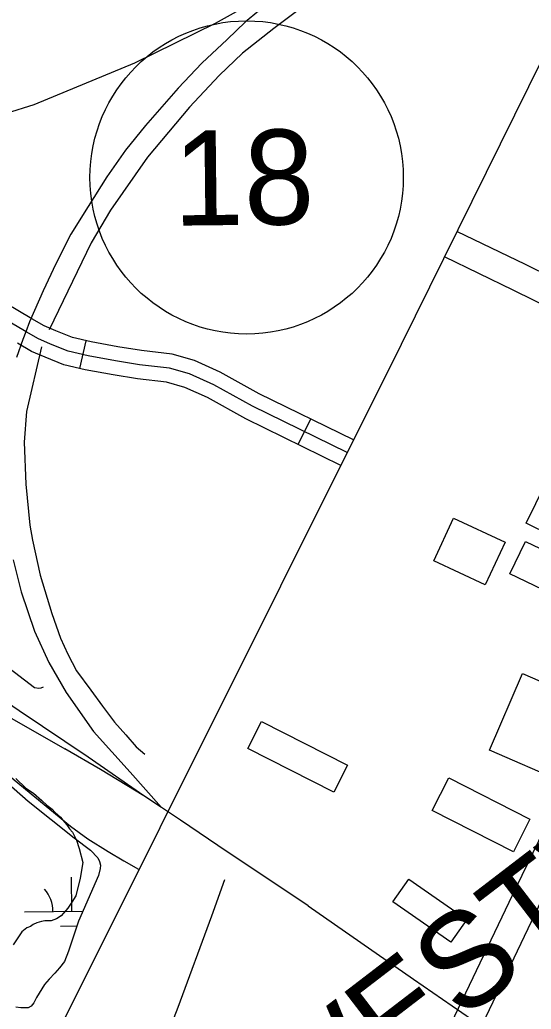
# Model space of a CAD drawing. Extents: x 3651524 to 3689615, y 505651 to 531377.
# Drawn here: x 3656690 to 3657229, y 514939 to 515981 of the extents above; entities that cross this region are included whole.
import ezdxf

# ---------------------------------------------------------------- set-up
doc = ezdxf.new("R2010")
doc.units = 0
for name, color, linetype in [('V-BLDG-OTLN', 7, 'Continuous'), ('V-CHAN-NAID', 7, 'Continuous'), ('V-RAIL-TRAK', 7, 'Continuous'), ('V-ROAD-CNTR', 7, 'Continuous'), ('V-ROAD-IDEN', 7, 'Continuous'), ('V-SITE-VEGE', 7, 'Continuous'), ('V-TOPO-SHOR', 7, 'Continuous'), ('V-WETL-SWMP', 7, 'Continuous')]:
    doc.layers.add(name, color=color, linetype=linetype)

msp = doc.modelspace()

# ---------------------------------------------------------------- linework, layer by layer
at = {"layer": 'V-BLDG-OTLN'}
for points in [[(3657357.467, 515385.145), (3657223.63, 515451.061), (3657254.288, 515513.313), (3657292.12, 515494.681), (3657274.796, 515459.504), (3657301.996, 515446.108), (3657309.987, 515462.334), (3657378.793, 515428.448)], [(3657201.339, 515431.182), (3657180.482, 515386.202), (3657126.287, 515411.332), (3657147.144, 515456.312)], [(3657335.971, 515335.602), (3657206.418, 515397.568), (3657222.827, 515431.874), (3657352.38, 515369.907)], [(3657219.76, 515292.521), (3657297.426, 515258.969), (3657262.587, 515178.324), (3657184.921, 515211.876)], [(3657021.078, 515167.723), (3656930.539, 515213.539), (3656944.981, 515242.077), (3657035.52, 515196.262)], [(3657210.063, 515104.874), (3657124.565, 515148.419), (3657142.036, 515182.722), (3657227.534, 515139.176)], [(3657099.87, 515076.061), (3657160.99, 515033.587), (3657144.295, 515009.562), (3657083.174, 515052.035)]]:
    msp.add_lwpolyline(points, close=True, dxfattribs=at)
at = {"layer": 'V-RAIL-TRAK'}
for points in [[(3657027.03, 516055.879), (3656964.812, 516016.027), (3656895.915, 515977.383), (3656811.245, 515935.815), (3656705.116, 515891.768), (3656588.044, 515855.281)], [(3656968.943, 516013.28), (3656927.987, 515979.378), (3656908.535, 515960.776), (3656882.145, 515935.698), (3656857.161, 515909.473), (3656822.648, 515870.01), (3656801.605, 515843.88), (3656781.987, 515815.814), (3656762.244, 515784.791), (3656744.036, 515755.576), (3656728.242, 515724.252), (3656714.936, 515695.947), (3656700.555, 515663.277), (3656696.596, 515652.758), (3656693.52, 515644.583), (3656686.884, 515625.7)], [(3656820.952, 515163.739), (3656762.412, 515204.408), (3656689.573, 515253.538), (3656620.506, 515300.41), (3656553.242, 515345.759), (3656473.403, 515400.984), (3656409.302, 515444.843), (3656315.785, 515507.174), (3656233.592, 515562.538), (3656163.614, 515606.648), (3656109.569, 515639.594), (3656060.358, 515666.98), (3655990.169, 515703.645), (3655925.596, 515734.771), (3655821.772, 515778.057), (3655754.041, 515802.254)], [(3656683.188, 515412.579), (3656691.695, 515378.693), (3656705.9, 515337.457), (3656720.701, 515304.117), (3656739.004, 515272.635), (3656767.983, 515231.561), (3656806.373, 515188.737), (3656839.343, 515151.588)], [(3656593.037, 515303.071), (3656633.64, 515275.476), (3656681.752, 515245.127), (3656737.529, 515213.397)], [(3656839.343, 515151.588), (3656820.952, 515163.739), (3656775.257, 515191.408), (3656737.529, 515213.397)], [(3656994.076, 515047.747), (3656898.764, 515111.405), (3656859.357, 515138.11), (3656839.343, 515151.588)], [(3656994.076, 515047.747), (3657105.069, 514970.799), (3657166.102, 514928.428), (3657251.364, 514871.481), (3657382.891, 514781.73), (3657445.666, 514738.898), (3657502.343, 514700.625), (3657624.534, 514620.046), (3657696.96, 514574.038), (3657732.292, 514553.056), (3657795.889, 514518.578), (3657843.355, 514494.899), (3657922.647, 514459.028), (3658024.488, 514414.992), (3658106.425, 514381.161), (3658188.117, 514347.101), (3658276.069, 514310.043), (3658352.66, 514278.241), (3658430.613, 514244.758), (3658553.331, 514191.666), (3658647.596, 514153.723), (3658745.038, 514111.927), (3658817.017, 514083.077)]]:
    msp.add_lwpolyline(points, dxfattribs=at)
at = {"layer": 'V-ROAD-CNTR'}
for p, q in [((3656753.363, 515614.091), (3656760.122, 515643.32)), ((3656983.59, 515533.901), (3656996.764, 515560.854))]:
    msp.add_line(p, q, dxfattribs=at)
for points in [[(3657821.364, 517115.979), (3657494.654, 516454.852), (3657091.838, 515639.148), (3656710.83, 514875.472), (3656430.01, 514305.598), (3656056.096, 513550.048), (3655742.777, 512921.615)], [(3655716.186, 515785.202), (3655800.868, 515755.908), (3655912.687, 515711.634), (3656007.159, 515667.133), (3656037.175, 515651.483), (3656067.596, 515635.258), (3656114.681, 515607.156), (3656202.069, 515549.224), (3656316.766, 515474.798), (3656450.209, 515383.084), (3656482.187, 515358.901), (3656506.308, 515337.065), (3656541.46, 515302.628), (3656616.681, 515239.917), (3656684.412, 515180.535), (3656743.501, 515131.86), (3656761.956, 515118.659), (3656783.335, 515105.334), (3656799.958, 515095.211), (3656815.427, 515086.576)], [(3657035.098, 515525.421), (3656935.269, 515574.216), (3656894.752, 515596.905), (3656869.132, 515608.237), (3656847.847, 515614.384), (3656816.351, 515618.054), (3656791.032, 515621.974), (3656762.352, 515627.408), (3656741.117, 515632.319), (3656722.665, 515639.819), (3656709.237, 515645.46), (3656695.297, 515653.555), (3656653.889, 515677.857), (3656523.525, 515769.898)], [(3657471.799, 515600.837), (3657222.975, 515723.684), (3657150.63, 515758.532)], [(3657458.71, 515573.843), (3657209.825, 515696.72), (3657137.61, 515731.505)], [(3657041.685, 515538.897), (3656942.232, 515587.508), (3656901.465, 515610.338), (3656874.27, 515622.366), (3656850.816, 515629.14), (3656818.367, 515632.921), (3656793.576, 515636.759), (3656765.439, 515642.09), (3656745.659, 515646.664), (3656728.394, 515653.682), (3656715.936, 515658.916), (3656702.86, 515666.509), (3656662.025, 515690.474)], [(3657028.511, 515511.945), (3656928.306, 515560.924), (3656888.039, 515583.472), (3656863.994, 515594.108), (3656844.878, 515599.628), (3656814.335, 515603.187), (3656788.488, 515607.189), (3656759.265, 515612.726), (3656736.575, 515617.974), (3656716.936, 515625.956), (3656702.538, 515632.004), (3656687.734, 515640.601)], [(3657458.709, 515573.845), (3657213.181, 515067.513), (3657071.929, 514772.098)], [(3657485.609, 515560.563), (3657240.21, 515054.497), (3657099.543, 514760.302)]]:
    msp.add_lwpolyline(points, dxfattribs=at)
at = {"layer": 'V-ROAD-IDEN'}
msp.add_circle((3656929.203, 515815.308), 165, dxfattribs=at)
msp.add_circle((3656929.203, 515815.308), 165, dxfattribs=at)
at = {"layer": 'V-SITE-VEGE'}
for p, q in [((3656686.036, 515182.241), (3656696.704, 515171.984)), ((3656696.704, 515171.984), (3656704.81, 515166.602)), ((3656704.81, 515166.602), (3656713.58, 515158.771)), ((3656713.58, 515158.771), (3656718.602, 515153.944)), ((3656718.602, 515153.944), (3656724.223, 515149.743)), ((3656724.223, 515149.743), (3656727.371, 515146.112)), ((3656727.371, 515146.112), (3656733.007, 515141.297)), ((3656733.007, 515141.297), (3656735.53, 515138.268)), ((3656735.53, 515138.268), (3656739.932, 515133.429)), ((3656739.932, 515133.429), (3656742.479, 515129.171)), ((3656742.479, 515129.171), (3656745.627, 515125.538)), ((3656745.627, 515125.538), (3656750.104, 515117.006)), ((3656750.104, 515117.006), (3656752.734, 515108.439)), ((3656752.734, 515108.439), (3656756.715, 515093.743)), ((3656756.715, 515093.743), (3656753.962, 515077.068)), ((3656753.962, 515077.068), (3656749.399, 515058.511)), ((3656745.224, 515051.656), (3656741.035, 515045.42)), ((3656749.399, 515058.511), (3656745.224, 515051.656)), ((3656741.035, 515045.42), (3656733.808, 515037.273)), ((3656712.992, 515031.326), (3656708.095, 515029.999)), ((3656716.674, 515032.014), (3656712.992, 515031.326)), ((3656723.443, 515032.147), (3656716.674, 515032.014)), ((3656728.944, 515034.101), (3656723.443, 515032.147)), ((3656733.808, 515037.273), (3656728.944, 515034.101)), ((3656692.275, 515020.457), (3656683.308, 515006.737)), ((3656697.728, 515024.87), (3656692.275, 515020.457)), ((3656701.396, 515026.175), (3656697.728, 515024.87)), ((3656704.438, 515028.082), (3656701.396, 515026.175)), ((3656708.095, 515029.999), (3656704.438, 515028.082))]:
    msp.add_line(p, q, dxfattribs=at)
at = {"layer": 'V-TOPO-SHOR'}
for points in [[(3657162.362, 516118.095), (3657069.52, 516056.163), (3656957.726, 515972.14), (3656924.682, 515946.382), (3656900.089, 515922.673), (3656869.113, 515889.227), (3656824.618, 515836.839), (3656785.874, 515780.98), (3656765.55, 515746.465), (3656721.19, 515654.647)], [(3656084.918, 515699.437), (3656180.053, 515642.654), (3656282.537, 515575.217), (3656321.795, 515548.397), (3656439.345, 515468.916), (3656553.404, 515387.182), (3656674.039, 515302.262), (3656705.75, 515278.017), (3656710.301, 515277.143), (3656712.851, 515277.598), (3656715.386, 515278.644)], [(3656713.058, 515637.024), (3656697.161, 515568.795), (3656694.787, 515536.59), (3656696.455, 515492.255), (3656700.858, 515448.972), (3656703.745, 515433.233)], [(3656703.745, 515433.233), (3656711.745, 515396.163), (3656723.961, 515355.841), (3656733.263, 515330.041), (3656740.773, 515313.069), (3656750.075, 515295.352), (3656764.958, 515275.208), (3656777.4, 515258.156), (3656790.034, 515241.309), (3656801.791, 515227.991), (3656812.744, 515215.441), (3656822.095, 515207.566)], [(3656905.863, 515075.462), (3656892.217, 515037.117), (3656856.733, 514940.923), (3656834.856, 514884.65)]]:
    msp.add_lwpolyline(points, dxfattribs=at)
at = {"layer": 'V-WETL-SWMP'}
for p, q in [((3656625.4, 515222.57), (3656699.139, 515158.086)), ((3656699.139, 515158.086), (3656747.665, 515119.539)), ((3656747.665, 515119.539), (3656764.696, 515106.581)), ((3656764.696, 515106.581), (3656772.365, 515098.507)), ((3656772.365, 515098.507), (3656774.229, 515094.619)), ((3656774.229, 515094.619), (3656775.111, 515090.708)), ((3656774.995, 515087.362), (3656773.211, 515079.845)), ((3656775.111, 515090.708), (3656774.995, 515087.362)), ((3656745.118, 515042.185), (3656744.73, 515078.183)), ((3656773.211, 515079.845), (3656752.151, 515031.941)), ((3656695.121, 515041.647), (3656756.709, 515042.31)), ((3656752.151, 515031.941), (3656741.716, 515000.025)), ((3656733.285, 515026.626), (3656750.474, 515026.811)), ((3656741.716, 515000.025), (3656737.261, 514989.101)), ((3656737.261, 514989.101), (3656732.112, 514982.486)), ((3656732.112, 514982.486), (3656727.131, 514977.056)), ((3656721.19, 514970.619), (3656716.214, 514964.991)), ((3656727.131, 514977.056), (3656721.19, 514970.619)), ((3656716.214, 514964.991), (3656707.895, 514951.22)), ((3656707.895, 514951.22), (3656705.08, 514945.645)), ((3656691.442, 514940.398), (3656686.111, 514941.252)), ((3656698.915, 514940.383), (3656691.442, 514940.398)), ((3656702.41, 514942.237), (3656698.915, 514940.383)), ((3656705.08, 514945.645), (3656702.41, 514942.237))]:
    msp.add_line(p, q, dxfattribs=at)
msp.add_arc((3656689.873, 515042.065), 35.246, 359.844867, 41.388526, dxfattribs=at)

# ---------------------------------------------------------------- texts
at = {"layer": 'V-CHAN-NAID'}
msp.add_text('WESTWEGO TRAFFIC LIGHT (101.4)', height=100, rotation=37.493815, dxfattribs=at).set_placement((3656984.322, 514794.391))
at = {"layer": 'V-ROAD-IDEN'}
msp.add_text('18', height=100, rotation=0.616684, dxfattribs=at).set_placement((3656852.186, 515764.476))

doc.saveas('drawing.dxf')
